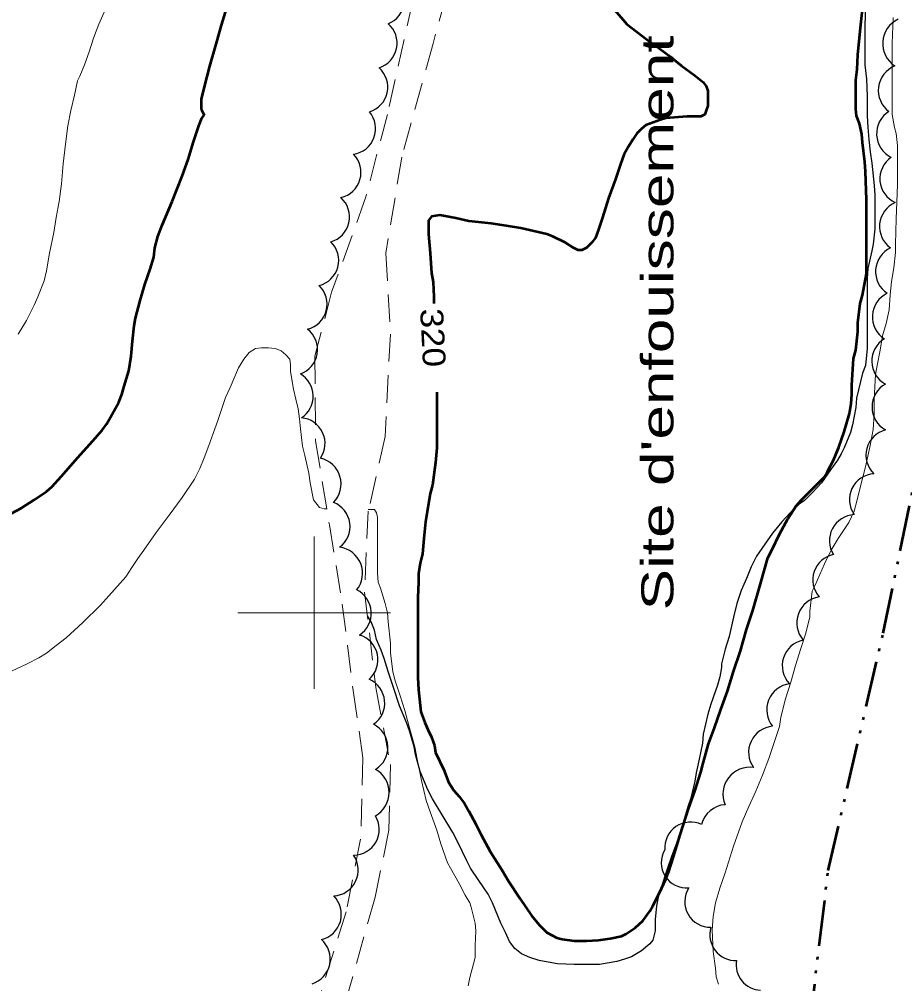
# Model space of a CAD drawing. Extents: x 240591 to 242335, y 5323482 to 5326937.
# Drawn here: x 240761.4 to 240877.4, y 5323951.4 to 5324077.8 of the extents above; entities that cross this region are included whole.
import ezdxf

# ---------------------------------------------------------------- set-up
doc = ezdxf.new("R2010")
doc.units = 0
doc.header["$LTSCALE"] = 1.2
for name, pattern in [('DASH_DOUBLE_DOT', [9.2, 5, -1.2, 0.3, -1.2, 0.3, -1.2]), ('LONG_DASH_SHORT_DASH', [9.9, 6, -1.2, 1.5, -1.2]), ('LONG_DASHED', [7.5, 6, -1.5]), ('MEDIUM_DASHED', [4.5, 3, -1.5])]:
    doc.linetypes.add(name, pattern=pattern)
for name, color, linetype, lineweight in [('1', 7, 'Continuous', 53), ('19', 7, 'Continuous', 13), ('2', 7, 'Continuous', 13), ('4', 7, 'DASH_DOUBLE_DOT', 53), ('44', 7, 'Continuous', 25), ('57', 7, 'LONG_DASH_SHORT_DASH', 25), ('61', 7, 'Continuous', 13)]:
    doc.layers.add(name, color=color, linetype=linetype, lineweight=lineweight)

msp = doc.modelspace()

# ---------------------------------------------------------------- linework, layer by layer
at = {"layer": '1', "linetype": 'LONG_DASHED'}
for points in [[(240788.8, 5324080.3), (240787.8, 5324077), (240787.2, 5324074.8), (240786.3, 5324071.6), (240785.6, 5324068.9), (240785.2, 5324067.3), (240785.2, 5324066), (240785.6, 5324065.2)], [(240759.7, 5324012.7), (240761.6, 5324013.7), (240763.3, 5324014.8), (240764.9, 5324015.9), (240765.6, 5324016.5), (240766.9, 5324017.9), (240769, 5324020.3), (240771, 5324022.5), (240772.2, 5324023.9), (240772.8, 5324024.7), (240773.3, 5324025.6), (240774.4, 5324027.6), (240774.8, 5324028.6), (240775.1, 5324029.7), (240775.7, 5324031.7), (240776, 5324033.6), (240776.2, 5324035.6), (240776.4, 5324037.6), (240776.6, 5324038.6), (240777.2, 5324040.9), (240777.8, 5324043), (240778.5, 5324045), (240779, 5324046.6), (240779.1, 5324047.8), (240779.5, 5324049.3), (240780.1, 5324050.8), (240781.4, 5324053.9), (240782.7, 5324057.2), (240783.5, 5324059.4), (240784.2, 5324061.7), (240784.9, 5324063.8), (240785.3, 5324064.8), (240785.6, 5324065.2)]]:
    msp.add_lwpolyline(points, dxfattribs=at)
at = {"layer": '1'}
for points in [[(240839.4, 5324079), (240840.5, 5324077.7), (240841, 5324077.1), (240842.3, 5324076.1), (240843.6, 5324075.1), (240844.8, 5324074.3), (240846.5, 5324073), (240848.1, 5324071.7), (240849.9, 5324070.4), (240851, 5324069.5), (240851.4, 5324069), (240851.6, 5324068.4), (240851.6, 5324067.7), (240851.6, 5324066.4), (240851.4, 5324065.8), (240851.2, 5324065.3), (240850.7, 5324065), (240850.2, 5324065), (240848.9, 5324065), (240846.1, 5324064.8), (240845.4, 5324064.6), (240843.5, 5324063.9), (240842.9, 5324063.4), (240842.3, 5324062.8), (240841.8, 5324062), (240841.2, 5324061.1), (240840.6, 5324060), (240840.2, 5324058.9), (240839.5, 5324056.8), (240838.6, 5324054.3), (240837.8, 5324051.8), (240837.3, 5324050.2), (240836.9, 5324049.1), (240836.4, 5324048.5), (240835.7, 5324047.8), (240835.1, 5324047.5), (240834.6, 5324047.5), (240834, 5324047.8), (240832.9, 5324048.5), (240831.3, 5324049.3), (240830.5, 5324049.6), (240828.8, 5324050), (240827.1, 5324050.4), (240825.2, 5324050.7), (240823.2, 5324051), (240820.3, 5324051.3), (240818.6, 5324051.7), (240816.5, 5324052.1), (240815.9, 5324052), (240815.4, 5324051.9), (240815, 5324051.4), (240815, 5324050.9), (240815, 5324049.6), (240815.2, 5324047.1), (240815.4, 5324044.5), (240815.6, 5324043.3), (240815.7, 5324041.4), (240815.7, 5324040.5)], [(240815.9, 5323981.7), (240817, 5323979.4), (240817.6, 5323977.8), (240818.3, 5323976.7), (240819, 5323975.9), (240819.7, 5323975), (240820.3, 5323974), (240821.2, 5323972.3), (240821.9, 5323970.9), (240823.1, 5323968.7), (240824.6, 5323966.3), (240825.5, 5323964.8), (240827, 5323962.5), (240828.5, 5323960.3), (240829.5, 5323959.1), (240830.5, 5323958.1), (240831.8, 5323957.4), (240832.5, 5323957.2), (240834.1, 5323957), (240835.7, 5323957), (240837.3, 5323957.1), (240838.8, 5323957.3), (240840.3, 5323957.6), (240840.9, 5323957.9), (240842.1, 5323958.7), (240843.1, 5323959.6), (240844, 5323960.9), (240844.4, 5323961.6), (240845.3, 5323963.3), (240846.1, 5323965.1), (240846.5, 5323966.1), (240847.1, 5323968), (240848, 5323970.9), (240849.1, 5323974.3), (240849.9, 5323976.6), (240850.7, 5323979.1), (240851, 5323980.3), (240851.7, 5323982.8), (240852.5, 5323984.9), (240853.3, 5323987.3), (240854.2, 5323989.7), (240855, 5323992.3), (240855.9, 5323995), (240856.7, 5323997.8), (240857.5, 5324000.3), (240858.5, 5324003.8), (240859.5, 5324007.2), (240860, 5324008.2), (240861, 5324010.3), (240862.1, 5324012.3), (240863.2, 5324014), (240863.8, 5324014.7), (240865.1, 5324016), (240866.9, 5324017.8), (240867.3, 5324018.5), (240868.1, 5324020), (240868.8, 5324021.7), (240869.5, 5324023.7), (240870.2, 5324026.1), (240870.4, 5324027.4), (240870.5, 5324028.6), (240870.5, 5324029.8), (240870.7, 5324033.3), (240871, 5324034.4), (240871.3, 5324036.8), (240871.3, 5324038), (240871.6, 5324040.5), (240871.9, 5324041.6), (240872.4, 5324044.4), (240872.4, 5324045.4), (240872.4, 5324047.6), (240872.4, 5324050.8), (240872.4, 5324054.1), (240872.3, 5324057.8), (240872.2, 5324059.1), (240871.9, 5324061.6), (240871.8, 5324062.7), (240871.5, 5324064.1), (240871.1, 5324065.1), (240871, 5324066), (240871, 5324067.5), (240871, 5324069.8), (240871.2, 5324071.2), (240871.3, 5324073.1), (240871.6, 5324076.2), (240871.9, 5324079.1)], [(240816.1, 5324028.9), (240816.1, 5324028.7), (240816.1, 5324026.9), (240816.1, 5324024.4), (240816.1, 5324021.6), (240815.9, 5324019.7), (240815.5, 5324016.7), (240815.2, 5324015.6), (240814.8, 5324013.2), (240814.6, 5324011.9), (240814.4, 5324009.7), (240814.2, 5324007.7), (240813.9, 5324006.5), (240813.7, 5324005.1), (240813.7, 5324004), (240813.6, 5324002), (240813.6, 5324000.3), (240813.6, 5323997.4)], [(240813.6, 5323997.4), (240813.6, 5323994.4), (240813.6, 5323991.5), (240813.7, 5323989.9), (240814, 5323987), (240814.5, 5323985.6), (240814.9, 5323984.7), (240815.4, 5323983.7), (240815.8, 5323982.6), (240815.9, 5323981.7)]]:
    msp.add_lwpolyline(points, dxfattribs=at)
at = {"layer": '19', "linetype": 'MEDIUM_DASHED'}
for points in [[(240820.2, 5324186.8), (240816.1, 5324172.5), (240813.4, 5324162.4), (240813.4, 5324152.3), (240815, 5324139.5), (240817.2, 5324125.4), (240820.4, 5324108.9), (240820.5, 5324099.6), (240818.8, 5324086.2), (240815.6, 5324074.6), (240811.5, 5324059.7), (240809.4, 5324047.1), (240810, 5324036.5), (240809.3, 5324023.1), (240807.1, 5324013.3), (240806.6, 5324002.7), (240808.1, 5323990.2), (240810, 5323980.1), (240809.8, 5323971.5), (240808, 5323962.7), (240804.3, 5323949.6)], [(240813, 5324080.4), (240809.6, 5324065.3), (240806.8, 5324054.5), (240802.3, 5324042), (240800.1, 5324033.6), (240800.2, 5324022.5), (240802, 5324011.5), (240803.7, 5324001.1), (240805.1, 5323989.8), (240806.4, 5323981), (240806.1, 5323970.3), (240804.2, 5323960.8), (240800.7, 5323949.6)]]:
    msp.add_lwpolyline(points, dxfattribs=at)
at = {"layer": '2', "linetype": 'LONG_DASHED'}
for points in [[(240761.2, 5324036.5), (240762.3, 5324038.3), (240763.3, 5324040.3), (240763.8, 5324041.4), (240764.6, 5324043.5), (240764.9, 5324044.8), (240765.3, 5324047.1), (240765.9, 5324049.8), (240766.2, 5324051.8), (240766.6, 5324053.9), (240766.9, 5324056.2), (240767.1, 5324058.8), (240767.4, 5324061.4), (240767.7, 5324063.8), (240768.1, 5324065.8), (240768.6, 5324067.8), (240769, 5324069.7), (240769.3, 5324070.3), (240769.9, 5324071.8), (240770.5, 5324073.5), (240771.1, 5324075.3), (240771.8, 5324077.1), (240772.5, 5324078.7)], [(240772, 5324001), (240773.1, 5324002.2), (240775.3, 5324004.7), (240776.1, 5324005.9), (240776.9, 5324007.1), (240777.7, 5324008.2), (240779.3, 5324010.5), (240781, 5324012.8), (240782.7, 5324015.1), (240784.3, 5324017.5), (240785, 5324018.9), (240785.6, 5324020.3), (240786.2, 5324021.9), (240787.4, 5324025.2), (240788.4, 5324028.2), (240789, 5324029.5), (240790.1, 5324032.1), (240790.8, 5324033.2), (240791.5, 5324034.1), (240792.3, 5324034.6), (240793.1, 5324034.7), (240794, 5324034.7), (240794.9, 5324034.6), (240795.7, 5324034.3), (240796.3, 5324033.8), (240796.8, 5324033.2), (240796.9, 5324032.5), (240796.9, 5324031.6), (240797.3, 5324029.3), (240797.6, 5324028), (240797.9, 5324026.7), (240798.1, 5324025.4), (240798.2, 5324024.1), (240798.5, 5324021.8), (240798.8, 5324020.6), (240799.3, 5324018.3), (240799.5, 5324017), (240799.9, 5324014.8)], [(240760.4, 5323992.4), (240762.4, 5323993.3), (240763.9, 5323994.1), (240764.9, 5323994.7), (240766.2, 5323995.7), (240767.5, 5323996.7), (240768.6, 5323997.7), (240769.7, 5323998.7), (240772, 5324001)]]:
    msp.add_lwpolyline(points, dxfattribs=at)
at = {"layer": '2'}
for points in [[(240853, 5323951.3), (240852.7, 5323952.3), (240852.6, 5323953.4), (240852.3, 5323955.6), (240852.2, 5323958.4), (240852.3, 5323960.2), (240852.6, 5323962), (240853.2, 5323963.9), (240853.9, 5323965.9), (240855, 5323969.4), (240856.1, 5323972.6), (240857, 5323974.6), (240857.9, 5323976.6), (240858.8, 5323978.7), (240859.6, 5323980.9), (240860.3, 5323983), (240861, 5323985.1), (240861.2, 5323986.3), (240861.8, 5323988.7), (240862.5, 5323990.9), (240863.1, 5323993.1), (240863.8, 5323995.3), (240864.4, 5323997.2), (240865, 5323999.4), (240865, 5324000.2), (240865.3, 5324002.8), (240865.7, 5324003.6), (240866.9, 5324006.4), (240867.8, 5324008.2), (240868.7, 5324009.7), (240870.1, 5324011.8), (240870.8, 5324013.3), (240871.2, 5324014.8), (240871.6, 5324016.4), (240872.3, 5324019.1), (240872.9, 5324021.9), (240873.3, 5324024), (240873.4, 5324026), (240873.4, 5324028), (240873.6, 5324031.2), (240873.8, 5324032.4), (240874.2, 5324034.4), (240874.5, 5324036.3), (240875, 5324037.9), (240875.4, 5324039.7), (240875.5, 5324041.6), (240875.7, 5324043.4), (240876, 5324045.2), (240876.2, 5324047.2), (240876.2, 5324048.3), (240876.3, 5324051.6), (240876.4, 5324053.8), (240876.5, 5324056.1), (240876.5, 5324058.1), (240876.5, 5324061.2), (240876.3, 5324062.8), (240876.1, 5324063.6), (240875.8, 5324065.3), (240875.8, 5324066.2), (240875.8, 5324068.8), (240875.8, 5324071.4), (240875.8, 5324074.6), (240875.9, 5324078)], [(240799.9, 5324014.8), (240800.7, 5324013.8), (240801.3, 5324013.6), (240801.7, 5324013.6)], [(240807.1, 5324013.5), (240807.9, 5324013.5), (240808.2, 5324013.1), (240808.3, 5324012.5), (240808.3, 5324011.1), (240808.3, 5324008.5), (240808.3, 5324005.2), (240808.4, 5324004), (240808.7, 5324003.2), (240809.3, 5324001.2), (240809.6, 5324000), (240809.7, 5323998.8), (240810, 5323996), (240810, 5323994.7), (240810.3, 5323992.3), (240810.6, 5323991.2), (240811.3, 5323989.1), (240811.9, 5323987.2), (240812.4, 5323985.2), (240813.2, 5323982.4), (240813.5, 5323980.8), (240814.1, 5323978), (240814.7, 5323975.4), (240815.2, 5323973.9), (240816.1, 5323971.5), (240816.6, 5323969.7), (240817.5, 5323967.2), (240817.9, 5323966.5), (240819, 5323964.5), (240819.8, 5323963), (240820.4, 5323962), (240820.6, 5323961.4), (240821.1, 5323959.3), (240821.2, 5323958.3), (240821.1, 5323956.4), (240821.1, 5323954.8), (240820.9, 5323954), (240820.4, 5323952.2), (240820.2, 5323951.1)]]:
    msp.add_lwpolyline(points, dxfattribs=at)
at = {"layer": '4'}
msp.add_lwpolyline([(240813.8, 5323894.5), (240837.9, 5323894.8), (240853.6, 5323903.1), (240863.6, 5323934.4), (240867.4, 5323966.2), (240874.6, 5323997.3), (240880.9, 5324027.7), (240887.7, 5324063.3), (240891.8, 5324094.2), (240896.6, 5324123.1), (240898.9, 5324148.6), (240898.9, 5324169.8), (240897.6, 5324189.2), (240897.7, 5324201.4)], dxfattribs=at)
at = {"layer": '44'}
for centre, radius, start, end in [((240802.75, 5324057.699), 3.395, 282.92825, 44.5436), ((240877.577, 5324056.856), 3.411, 124.39926, 246.00702), ((240801.234, 5324051.863), 3.401, 286.32902, 47.98547), ((240799.84, 5324046.164), 3.385, 284.02035, 46.02955), ((240877.014, 5324044.703), 3.413, 114.84881, 236.69259), ((240798.302, 5324040.432), 3.399, 284.4501, 46.0726), ((240876.601, 5324038.76), 3.418, 115.30408, 237.41181), ((240797.049, 5324034.474), 3.395, 289.81613, 51.76696), ((240875.746, 5324020.653), 3.401, 104.23335, 225.91624), ((240801.325, 5324011.284), 3.386, 306.7304, 68.79122), ((240802.912, 5324005.156), 3.442, 320.80334, 82.69341), ((240804.116, 5323999.922), 3.391, 302.75099, 64.41375), ((240804.975, 5323993.821), 3.392, 311.21369, 73.29945), ((240864.798, 5323993.055), 3.425, 101.59039, 223.65594), ((240805.864, 5323988.156), 3.393, 304.79794, 66.62324)]:
    msp.add_arc(centre, radius, start, end, dxfattribs=at)
for centre, major_axis, ratio, start_param, end_param in [((240808.463, 5324080.346), (3.367, -0.468), 0.999977, 5.2231748, 7.3458945), ((240807.48, 5324074.623), (3.331, -0.666), 0.995837, 5.2201137, 7.3383115), ((240878.054, 5324074.582), (-3.514, 0.234), 0.997664, 5.2199486, 7.3425274), ((240877.399, 5324068.446), (-3.347, 0.783), 0.999596, 5.3201484, 7.4488195), ((240806.256, 5324068.872), (3.318, -0.784), 0.993996, 5.2421228, 7.3580995), ((240804.677, 5324063.434), (3.173, -1.194), 0.999994, 5.2180728, 7.3475448), ((240877.181, 5324062.756), (1.886, -2.883), 0.999995, 3.1192065, 5.2434807), ((240877.544, 5324050.599), (-3.368, 0.601), 0.999255, 5.2956286, 7.419258), ((240876.577, 5324032.964), (-3.478, -0.072), 0.983182, 5.2412593, 7.3339555), ((240796.534, 5324028.36), (-1.345, 3.086), 0.997984, 3.3011199, 5.3525316), ((240876.577, 5324026.955), (-3.437, -0.01), 0.999729, 5.2159855, 7.344737), ((240798.063, 5324022.171), (-1.515, 3.015), 0.9996, 3.6376634, 5.7320623), ((240800.063, 5324016.857), (3.326, 0.998), 0.998604, 5.2199886, 7.3400578), ((240873.578, 5324014.814), (-3.068, 1.476), 0.999046, 5.218461, 7.3473731), ((240870.97, 5324009.444), (-1.473, -3.076), 0.999937, 3.6378541, 5.7246223), ((240868.76, 5324004.29), (1.161, -3.191), 0.999883, 2.9912956, 5.0798327), ((240866.72, 5323998.656), (-3.23, 1.193), 0.999994, 5.2177186, 7.3476982), ((240862.774, 5323987.286), (-3.07, 1.541), 0.999494, 5.3100657, 7.4312787), ((240806.256, 5323982.35), (3.407, 0.088), 0.993995, 5.2413341, 7.3581699), ((240860.393, 5323981.708), (-3.075, 1.524), 0.996907, 5.2541305, 7.3713101), ((240806.361, 5323976.441), (3.427, -0.538), 0.999832, 5.369997, 7.5012146), ((240857.111, 5323976.223), (-2.809, 2.126), 0.996692, 5.21357, 7.3369259), ((240854.102, 5323971.443), (-1.412, -3.097), 0.99986, 3.6349106, 4.9048758), ((240805.15, 5323971.611), (2.97, -1.641), 0.999036, 5.2228063, 7.3443421), ((240849.356, 5323969.164), (-2.875, -1.803), 0.999984, 3.7135905, 5.791914), ((240802.381, 5323966.275), (3.061, -1.482), 0.999858, 5.218878, 7.3429373), ((240848.89, 5323967.29), (-2.72, -2.034), 0.983529, 5.1231484, 7.2848028), ((240851.975, 5323962.153), (-2.722, -2.042), 0.991339, 5.0791408, 7.2307654), ((240800.169, 5323960.475), (3.162, -1.249), 0.999585, 5.3233506, 7.4456823), ((240855.272, 5323957.794), (-1.962, -2.768), 0.99781, 5.0360285, 6.9355399), ((240798.724, 5323954.62), (3.297, -0.824), 0.997368, 5.2570918, 7.3800143), ((240858.723, 5323953.882), (-2.989, -1.624), 0.982656, 5.6144268, 7.3004285)]:
    msp.add_ellipse(centre, major_axis=major_axis, ratio=ratio, start_param=start_param, end_param=end_param, dxfattribs=at)
at = {"layer": '57'}
for points in [[(240872.3, 5324079.3), (240872.2, 5324077), (240872.2, 5324073.9), (240872.2, 5324071.8), (240872.4, 5324069.9), (240872.5, 5324067.7), (240872.5, 5324066.5), (240872.5, 5324065.1), (240872.6, 5324063.6), (240872.7, 5324062), (240872.9, 5324060.4), (240873.1, 5324058.9), (240873.4, 5324056), (240873.5, 5324054.7), (240873.5, 5324053.5), (240873.5, 5324050.3), (240873.3, 5324048.3), (240873.1, 5324047.4), (240872.6, 5324045.1), (240872.5, 5324043.8), (240872.5, 5324042.6), (240872.5, 5324040), (240872.5, 5324037.2), (240872.5, 5324034.6), (240872.3, 5324032.4), (240871.9, 5324031.4), (240871.1, 5324028.1), (240871, 5324026.9), (240870.6, 5324024.6), (240870.3, 5324023.6), (240869.5, 5324021.6), (240869.1, 5324020.8), (240868.6, 5324020), (240867.7, 5324018.7), (240866.5, 5324017), (240865.4, 5324015.8), (240864.3, 5324014.7), (240863.6, 5324014.2), (240862.4, 5324013.1), (240861.3, 5324011.9), (240860.1, 5324010.4), (240858, 5324007.4), (240857.3, 5324006), (240856.7, 5324004.5), (240856, 5324002.9), (240855.4, 5324001.2), (240855, 5323999.4), (240854.4, 5323996.9), (240853.9, 5323995.2), (240853.4, 5323993.3), (240853.4, 5323992.8), (240853.2, 5323991.6), (240852.9, 5323990.5), (240852, 5323988), (240851.6, 5323986.7)], [(240851.6, 5323986.7), (240851.3, 5323985.4), (240851, 5323984.1), (240850.9, 5323982.9), (240850.5, 5323980.8), (240850.1, 5323979), (240849.9, 5323977.9), (240849.4, 5323975.7), (240849.1, 5323974.8), (240848.4, 5323972.5), (240847.5, 5323969.8), (240846.8, 5323967.9), (240846.3, 5323966.4), (240845.5, 5323964), (240845.1, 5323962.7), (240844.9, 5323961.6), (240844.7, 5323959.8), (240844.7, 5323958.3), (240844.4, 5323957.1), (240844, 5323956.6), (240842.9, 5323955.7), (240841.6, 5323954.9), (240840.7, 5323954.6), (240839.7, 5323954.3), (240837.4, 5323953.9), (240836.3, 5323953.9), (240834.1, 5323953.9), (240831.9, 5323954), (240830.7, 5323954.2), (240829.5, 5323954.4), (240828.3, 5323954.8), (240827.2, 5323955.3), (240826.3, 5323956), (240825.6, 5323956.9), (240825.1, 5323958.1), (240824.5, 5323959.3), (240823.4, 5323962), (240822.8, 5323963.1), (240821.6, 5323964.9), (240820.5, 5323966.5), (240820, 5323967.5), (240818.8, 5323970), (240818.2, 5323971.2), (240816.8, 5323973.5), (240815.5, 5323975.6), (240814.9, 5323976.8), (240813.9, 5323979.2), (240813.3, 5323981.4), (240813.1, 5323982.4), (240812.5, 5323984.5), (240812.1, 5323985.6), (240811.2, 5323987.8), (240810.4, 5323990.2), (240809.7, 5323992.3), (240809.2, 5323994), (240808.8, 5323995.1), (240808.2, 5323996.5), (240807.9, 5323997.7), (240807.5, 5323998.8), (240807, 5323999.6)]]:
    msp.add_lwpolyline(points, dxfattribs=at)
at = {"layer": '61'}
for points in [[(240800, 5324010), (240800, 5324000), (240800, 5323990)], [(240790, 5324000), (240800, 5324000), (240810, 5324000)]]:
    msp.add_lwpolyline(points, dxfattribs=at)

# ---------------------------------------------------------------- texts
at = {"layer": '1', "width": 1.15}
msp.add_text('320', height=3, rotation=272.916, dxfattribs=at).set_placement((240813.9, 5324039.8))
at = {"layer": '57', "width": 1.45}
msp.add_text("Site d'enfouissement", height=4.2, rotation=90, dxfattribs=at).set_placement((240847.1, 5324000.3))

doc.saveas('drawing.dxf')
